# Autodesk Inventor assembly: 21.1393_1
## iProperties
Created: 2011-07
Part Number: 21.1393_1
Document SubType Name: Assembly
Designer: Administrator
Description: POWER-LOCK BODY WITH SET SCREW
Mass: 19.9854 g
Surface Area: 23.7668 cm^2
Volume: 2.545 cm^3
Density: 7.85281 g/cm^3
Author: Administrator
